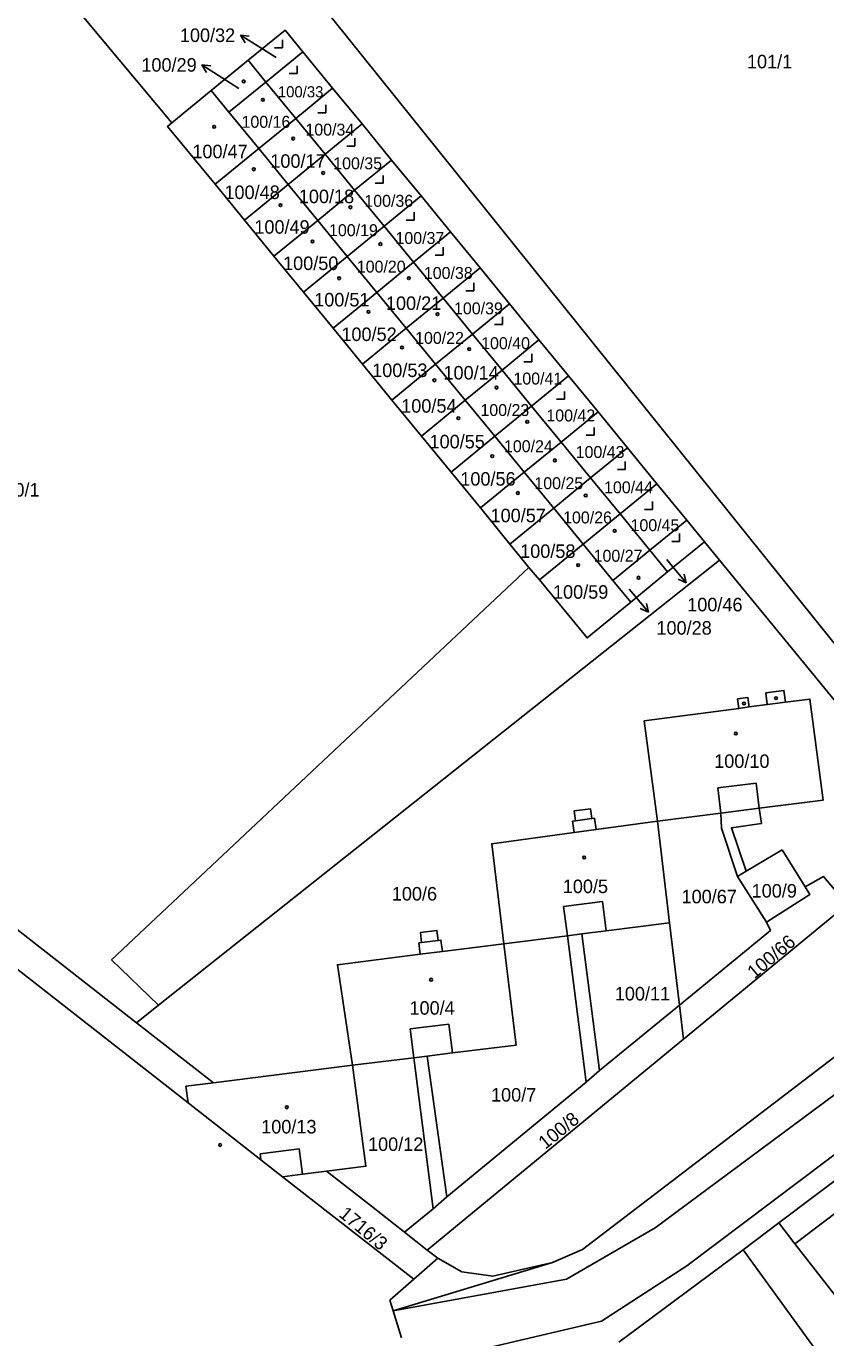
# Model space of a CAD drawing. Extents: x -724107 to -720612, y -1045267 to -1038441.
# Drawn here: x -723405.8 to -723305.3, y -1042643.6 to -1042478.7 of the extents above; entities that cross this region are included whole.
import ezdxf

# ---------------------------------------------------------------- set-up
doc = ezdxf.new("R2010")
doc.units = 0
for name, color, linetype in [('Hranice kat_území', 7, 'Continuous'), ('Hranice parcel', 7, 'Continuous'), ('Parcelní čísla', 7, 'Continuous'), ('Pop  PČ popisy', 7, 'Continuous'), ('Vnitřní kresba', 7, 'Continuous'), ('Značky budov', 7, 'Continuous'), ('Značky kultur', 7, 'Continuous')]:
    doc.layers.add(name, color=color, linetype=linetype)

msp = doc.modelspace()

# ---------------------------------------------------------------- linework, layer by layer
at = {"layer": 'Hranice kat_území'}
for p, q in [((-723432.73, -1042577.07), (-723385.46, -1042614.08)), ((-723373.58, -1042623.38), (-723357.09, -1042636.28)), ((-723357.09, -1042636.28), (-723360.11, -1042638.92))]:
    msp.add_line(p, q, dxfattribs=at)
for points in [[(-723373.58, -1042623.38), (-723376.31, -1042621.25), (-723385.46, -1042614.08)], [(-723360.11, -1042638.92), (-723359.7, -1042640.27), (-723358.63, -1042643.66)]]:
    msp.add_lwpolyline(points, dxfattribs=at)
at = {"layer": 'Hranice parcel'}
for p, q in [((-723387.48, -1042490.81), (-723402.99, -1042472.24)), ((-723375.68, -1042485.69), (-723371.04, -1042481.88)), ((-723371.04, -1042481.88), (-723367.29, -1042486.45)), ((-723377.91, -1042482.96), (-723382.55, -1042486.77)), ((-723375.68, -1042485.69), (-723377.91, -1042482.96)), ((-723375.68, -1042485.69), (-723380.32, -1042489.49)), ((-723371.93, -1042490.26), (-723375.68, -1042485.69)), ((-723387.48, -1042490.81), (-723382.55, -1042486.77)), ((-723382.55, -1042486.77), (-723380.32, -1042489.49)), ((-723371.93, -1042490.26), (-723367.29, -1042486.45)), ((-723367.29, -1042486.45), (-723363.59, -1042490.97)), ((-723380.32, -1042489.49), (-723376.57, -1042494.06)), ((-723376.57, -1042494.06), (-723371.93, -1042490.26)), ((-723368.23, -1042494.77), (-723371.93, -1042490.26)), ((-723368.23, -1042494.77), (-723363.59, -1042490.97)), ((-723363.59, -1042490.97), (-723359.88, -1042495.5)), ((-723382.07, -1042498.56), (-723376.57, -1042494.06)), ((-723376.57, -1042494.06), (-723372.87, -1042498.58)), ((-723372.87, -1042498.58), (-723368.23, -1042494.77)), ((-723364.53, -1042499.3), (-723368.23, -1042494.77)), ((-723364.53, -1042499.3), (-723359.88, -1042495.5)), ((-723359.88, -1042495.5), (-723356.18, -1042500.02)), ((-723378.36, -1042503.08), (-723382.07, -1042498.56)), ((-723378.36, -1042503.08), (-723372.87, -1042498.58)), ((-723372.87, -1042498.58), (-723369.17, -1042503.1)), ((-723369.17, -1042503.1), (-723364.53, -1042499.3)), ((-723360.82, -1042503.82), (-723364.53, -1042499.3)), ((-723360.82, -1042503.82), (-723356.18, -1042500.02)), ((-723356.18, -1042500.02), (-723352.47, -1042504.54)), ((-723374.66, -1042507.6), (-723378.36, -1042503.08)), ((-723374.66, -1042507.6), (-723369.17, -1042503.1)), ((-723369.17, -1042503.1), (-723365.46, -1042507.62)), ((-723365.46, -1042507.62), (-723360.82, -1042503.82)), ((-723357.11, -1042508.35), (-723360.82, -1042503.82)), ((-723357.11, -1042508.35), (-723352.47, -1042504.54)), ((-723352.47, -1042504.54), (-723348.76, -1042509.07)), ((-723370.95, -1042512.12), (-723374.66, -1042507.6)), ((-723370.95, -1042512.12), (-723365.46, -1042507.62)), ((-723365.46, -1042507.62), (-723361.75, -1042512.15)), ((-723361.75, -1042512.15), (-723357.11, -1042508.35)), ((-723353.4, -1042512.87), (-723357.11, -1042508.35)), ((-723353.4, -1042512.87), (-723348.76, -1042509.07)), ((-723348.76, -1042509.07), (-723345.05, -1042513.59)), ((-723367.24, -1042516.65), (-723370.95, -1042512.12)), ((-723367.24, -1042516.65), (-723361.75, -1042512.15)), ((-723361.75, -1042512.15), (-723358.04, -1042516.67)), ((-723358.04, -1042516.67), (-723353.4, -1042512.87)), ((-723349.7, -1042517.4), (-723353.4, -1042512.87)), ((-723349.7, -1042517.4), (-723345.05, -1042513.59)), ((-723345.05, -1042513.59), (-723341.35, -1042518.12)), ((-723363.53, -1042521.17), (-723367.24, -1042516.65)), ((-723363.53, -1042521.17), (-723358.04, -1042516.67)), ((-723358.04, -1042516.67), (-723354.34, -1042521.2)), ((-723349.7, -1042517.4), (-723354.34, -1042521.2)), ((-723345.99, -1042521.92), (-723349.7, -1042517.4)), ((-723345.99, -1042521.92), (-723341.35, -1042518.12)), ((-723341.35, -1042518.12), (-723337.64, -1042522.64)), ((-723359.83, -1042525.7), (-723363.53, -1042521.17)), ((-723359.83, -1042525.7), (-723354.34, -1042521.2)), ((-723354.34, -1042521.2), (-723350.63, -1042525.72)), ((-723350.63, -1042525.72), (-723345.99, -1042521.92)), ((-723342.28, -1042526.45), (-723345.99, -1042521.92)), ((-723342.28, -1042526.45), (-723337.64, -1042522.64)), ((-723337.64, -1042522.64), (-723333.93, -1042527.17)), ((-723356.12, -1042530.22), (-723359.83, -1042525.7)), ((-723356.12, -1042530.22), (-723350.63, -1042525.72)), ((-723350.63, -1042525.72), (-723346.92, -1042530.25)), ((-723346.92, -1042530.25), (-723342.28, -1042526.45)), ((-723338.57, -1042530.97), (-723342.28, -1042526.45)), ((-723338.57, -1042530.97), (-723333.93, -1042527.17)), ((-723333.93, -1042527.17), (-723330.22, -1042531.69)), ((-723352.41, -1042534.75), (-723356.12, -1042530.22)), ((-723352.41, -1042534.75), (-723346.92, -1042530.25)), ((-723346.92, -1042530.25), (-723343.21, -1042534.77)), ((-723343.21, -1042534.77), (-723338.57, -1042530.97)), ((-723334.86, -1042535.49), (-723338.57, -1042530.97)), ((-723334.86, -1042535.49), (-723330.22, -1042531.69)), ((-723330.22, -1042531.69), (-723326.52, -1042536.22)), ((-723348.7, -1042539.27), (-723352.41, -1042534.75)), ((-723348.7, -1042539.27), (-723343.21, -1042534.77)), ((-723343.21, -1042534.77), (-723339.49, -1042539.31)), ((-723339.49, -1042539.31), (-723334.86, -1042535.49)), ((-723331.16, -1042540.02), (-723334.86, -1042535.49)), ((-723331.16, -1042540.02), (-723326.52, -1042536.22)), ((-723326.52, -1042536.22), (-723322.77, -1042540.79)), ((-723345, -1042543.8), (-723348.7, -1042539.27)), ((-723345, -1042543.8), (-723339.49, -1042539.31)), ((-723339.49, -1042539.31), (-723335.8, -1042543.82)), ((-723335.8, -1042543.82), (-723331.16, -1042540.02)), ((-723327.41, -1042544.59), (-723331.16, -1042540.02)), ((-723327.41, -1042544.59), (-723322.77, -1042540.79)), ((-723322.77, -1042540.79), (-723320.54, -1042543.51)), ((-723325.18, -1042547.31), (-723320.54, -1042543.51)), ((-723342.61, -1042546.74), (-723345, -1042543.8)), ((-723341.29, -1042548.32), (-723335.8, -1042543.82)), ((-723335.8, -1042543.82), (-723332.05, -1042548.39)), ((-723332.05, -1042548.39), (-723327.41, -1042544.59)), ((-723325.18, -1042547.31), (-723327.41, -1042544.59)), ((-723342.61, -1042546.74), (-723341.29, -1042548.32)), ((-723332.05, -1042548.39), (-723329.82, -1042551.12)), ((-723329.82, -1042551.12), (-723325.18, -1042547.31)), ((-723318.48, -1042577.65), (-723326.47, -1042578.68)), ((-723318.48, -1042577.65), (-723313.67, -1042577.03)), ((-723326.47, -1042578.68), (-723324.94, -1042591.45)), ((-723310.8, -1042582.25), (-723307.88, -1042586.93)), ((-723316.38, -1042585.61), (-723312.74, -1042591.36)), ((-723324.94, -1042591.45), (-723323.7, -1042601.79)), ((-723345.76, -1042594.07), (-723337.78, -1042593.07)), ((-723337.78, -1042593.07), (-723335.95, -1042592.84)), ((-723323.19, -1042606.08), (-723323.7, -1042601.79)), ((-723382.28, -1042611.57), (-723391.94, -1042604.01)), ((-723323.19, -1042606.08), (-723355.39, -1042632.61)), ((-723364.8, -1042609.37), (-723382.28, -1042611.57)), ((-723364.8, -1042609.37), (-723357.1, -1042608.42)), ((-723357.1, -1042608.42), (-723355.4, -1042608.21)), ((-723300.57, -1042621.17), (-723311.19, -1042629.17)), ((-723311.19, -1042629.17), (-723315.69, -1042632.56)), ((-723358.24, -1042630.37), (-723355.39, -1042632.61)), ((-723354.07, -1042633.64), (-723355.39, -1042632.61)), ((-723315.69, -1042632.56), (-723331.32, -1042644.18)), ((-723315.69, -1042632.56), (-723280.06, -1042681.61)), ((-723354.07, -1042633.64), (-723357.09, -1042636.28))]:
    msp.add_line(p, q, dxfattribs=at)
for points in [[(-723278.64, -1042588.16), (-723334.54, -1042518.55), (-723369.16, -1042475.43), (-723362.99, -1042470.47), (-723371.61, -1042456.04)], [(-723377.91, -1042482.96), (-723373.27, -1042479.16), (-723371.04, -1042481.88)], [(-723382.07, -1042498.56), (-723388.04, -1042491.27), (-723387.48, -1042490.81)], [(-723320.54, -1042543.51), (-723318.65, -1042545.82), (-723281.64, -1042590.99)], [(-723391.94, -1042604.01), (-723389.18, -1042601.82), (-723395.07, -1042596.1), (-723342.61, -1042546.74)], [(-723341.29, -1042548.32), (-723335.31, -1042555.62), (-723329.82, -1042551.12)], [(-723474.38, -1042557.93), (-723460.4, -1042561.1), (-723444.26, -1042566.75), (-723430.26, -1042574.04), (-723391.94, -1042604.01)], [(-723313.67, -1042577.03), (-723305.63, -1042576), (-723307.3, -1042563.3), (-723310.37, -1042563.7), (-723310.57, -1042562.22), (-723312.85, -1042562.52), (-723312.65, -1042564), (-723314.93, -1042564.3), (-723315.09, -1042563.11), (-723316.38, -1042563.28), (-723316.22, -1042564.47), (-723328.13, -1042566.04), (-723326.47, -1042578.68)], [(-723326.47, -1042578.68), (-723334.17, -1042579.72), (-723334.37, -1042578.29), (-723334.71, -1042578.34), (-723334.88, -1042577.1), (-723336.94, -1042577.38), (-723336.78, -1042578.62), (-723337.12, -1042578.66), (-723336.93, -1042580.09), (-723347.29, -1042581.49), (-723345.76, -1042594.07)], [(-723318.48, -1042577.65), (-723318.41, -1042579.54), (-723316.38, -1042585.61)], [(-723313.67, -1042577.03), (-723313.4, -1042578.95), (-723317.16, -1042579.48), (-723315.29, -1042584.95), (-723310.8, -1042582.25)], [(-723307.88, -1042586.93), (-723305.58, -1042585.62), (-723302.61, -1042589.13), (-723323.19, -1042606.08)], [(-723312.74, -1042591.36), (-723307.29, -1042587.88), (-723307.88, -1042586.93)], [(-723335.95, -1042592.84), (-723332.89, -1042592.45), (-723324.94, -1042591.45)], [(-723323.7, -1042601.79), (-723312.27, -1042592.41), (-723312.74, -1042591.36)], [(-723345.76, -1042594.07), (-723353.5, -1042595.05), (-723353.68, -1042593.62), (-723354.03, -1042593.66), (-723354.19, -1042592.41), (-723356.26, -1042592.68), (-723356.1, -1042593.92), (-723356.45, -1042593.97), (-723356.27, -1042595.4), (-723366.68, -1042596.72), (-723364.8, -1042609.37)], [(-723355.4, -1042608.21), (-723352.93, -1042625.91), (-723335.41, -1042611.47), (-723337.78, -1042593.07)], [(-723323.7, -1042601.79), (-723333.75, -1042610.04), (-723335.95, -1042592.84)], [(-723355.4, -1042608.21), (-723352.22, -1042607.81), (-723344.24, -1042606.82), (-723345.76, -1042594.07)], [(-723294.52, -1042600.92), (-723335.88, -1042632.52), (-723339.65, -1042634.17), (-723347.17, -1042635.89), (-723351.03, -1042635.33), (-723354.07, -1042633.64)], [(-723364.8, -1042609.37), (-723363.1, -1042622.06), (-723368.08, -1042622.68)], [(-723357.1, -1042608.42), (-723354.65, -1042627.43), (-723358.24, -1042630.37)], [(-723382.28, -1042611.57), (-723385.74, -1042612.01), (-723385.46, -1042614.08)], [(-723373.58, -1042623.38), (-723371.09, -1042623.06), (-723368.08, -1042622.68)], [(-723368.08, -1042622.68), (-723362.42, -1042627.1), (-723358.24, -1042630.37)], [(-723287.28, -1042639.43), (-723289.61, -1042641.12), (-723289.94, -1042640.64), (-723294.84, -1042644.9), (-723297.04, -1042644.34), (-723301.77, -1042638.11), (-723303.31, -1042639.32), (-723309.2, -1042631.82), (-723311.19, -1042629.17)]]:
    msp.add_lwpolyline(points, dxfattribs=at)
at = {"layer": 'Pop  PČ popisy'}
for p, q in [((-723376.33, -1042481.4), (-723378.88, -1042479.81)), ((-723378.88, -1042479.81), (-723377.76, -1042479.92)), ((-723378.88, -1042479.81), (-723378.29, -1042480.77)), ((-723374.4, -1042482.6), (-723376.33, -1042481.4)), ((-723381.19, -1042485.16), (-723383.71, -1042483.53)), ((-723383.71, -1042483.53), (-723382.59, -1042483.65)), ((-723383.71, -1042483.53), (-723383.14, -1042484.49)), ((-723379.09, -1042486.51), (-723381.19, -1042485.16)), ((-723325.28, -1042545.76), (-723324.77, -1042546.38)), ((-723324.77, -1042546.38), (-723322.84, -1042548.68)), ((-723322.84, -1042548.68), (-723323.87, -1042548.23)), ((-723322.84, -1042548.68), (-723323.1, -1042547.59)), ((-723330.01, -1042549.5), (-723329.52, -1042550.08)), ((-723329.52, -1042550.08), (-723327.59, -1042552.38)), ((-723327.59, -1042552.38), (-723327.85, -1042551.29)), ((-723327.59, -1042552.38), (-723328.62, -1042551.93))]:
    msp.add_line(p, q, dxfattribs=at)
at = {"layer": 'Vnitřní kresba'}
for p, q in [((-723389.18, -1042601.82), (-723318.65, -1042545.82)), ((-723326.74, -1042629.82), (-723233.53, -1042560.48)), ((-723316.22, -1042564.47), (-723314.93, -1042564.3)), ((-723312.65, -1042564), (-723310.37, -1042563.7)), ((-723322.77, -1042634.57), (-723231.75, -1042565.97)), ((-723318.89, -1042574.47), (-723314.07, -1042573.86)), ((-723318.48, -1042577.65), (-723318.89, -1042574.47)), ((-723314.07, -1042573.86), (-723313.67, -1042577.03)), ((-723336.93, -1042580.09), (-723334.17, -1042579.72)), ((-723336.78, -1042578.62), (-723334.71, -1042578.34)), ((-723316.38, -1042585.61), (-723315.29, -1042584.95)), ((-723338.25, -1042589.38), (-723333.36, -1042588.76)), ((-723337.78, -1042593.07), (-723338.25, -1042589.38)), ((-723333.36, -1042588.76), (-723332.89, -1042592.45)), ((-723356.1, -1042593.92), (-723354.03, -1042593.66)), ((-723356.27, -1042595.4), (-723353.5, -1042595.05)), ((-723352.67, -1042604.19), (-723357.55, -1042604.8)), ((-723352.22, -1042607.81), (-723352.67, -1042604.19)), ((-723357.55, -1042604.8), (-723357.1, -1042608.42)), ((-723335.41, -1042611.47), (-723333.75, -1042610.04)), ((-723371.49, -1042619.89), (-723376.4, -1042620.51)), ((-723376.4, -1042620.51), (-723376.31, -1042621.25)), ((-723371.09, -1042623.06), (-723371.49, -1042619.89)), ((-723354.65, -1042627.43), (-723352.93, -1042625.91)), ((-723309.2, -1042631.82), (-723301.51, -1042625.97)), ((-723337.88, -1042636.28), (-723326.74, -1042629.82)), ((-723359.7, -1042640.27), (-723339.65, -1042634.17)), ((-723322.77, -1042634.57), (-723333.49, -1042641.53)), ((-723337.88, -1042636.28), (-723359.7, -1042640.27)), ((-723333.49, -1042641.53), (-723357.59, -1042647.22))]:
    msp.add_line(p, q, dxfattribs=at)
at = {"layer": 'Značky budov'}
for centre in [(-723378.47, -1042485.61), (-723376.06, -1042487.93), (-723382.19, -1042491.33), (-723372.25, -1042492.81), (-723377.2, -1042496.67), (-723368.47, -1042497.13), (-723373.84, -1042501.19), (-723365.06, -1042501.45), (-723369.83, -1042505.76), (-723361.29, -1042506.07), (-723366.47, -1042510.38), (-723357.71, -1042510.37), (-723362.79, -1042514.61), (-723354.1, -1042514.9), (-723358.57, -1042519.08), (-723350.12, -1042519.28), (-723354.5, -1042523.21), (-723346.68, -1042524.13), (-723351.49, -1042527.97), (-723342.82, -1042528.42), (-723347.22, -1042532.75), (-723339.35, -1042533.28), (-723344, -1042537.39), (-723335.48, -1042537.71), (-723331.84, -1042542.13), (-723336.43, -1042546.45), (-723328.83, -1042548.04), (-723311.56, -1042563.19), (-723315.58, -1042563.85), (-723316.61, -1042567.64), (-723335.66, -1042583.22), (-723354.92, -1042598.6), (-723373.05, -1042614.65), (-723381.43, -1042619.39)]:
    msp.add_circle(centre, 0.175, dxfattribs=at)
at = {"layer": 'Značky kultur'}
for p, q in [((-723373.6, -1042481.4), (-723373.6, -1042480.4)), ((-723374.6, -1042481.4), (-723373.6, -1042481.4)), ((-723371.74, -1042484.64), (-723371.74, -1042483.64)), ((-723372.74, -1042484.64), (-723371.74, -1042484.64)), ((-723368.13, -1042489.57), (-723368.13, -1042488.57)), ((-723369.13, -1042489.57), (-723368.13, -1042489.57)), ((-723365.51, -1042493.74), (-723364.51, -1042493.74)), ((-723364.51, -1042493.74), (-723364.51, -1042492.74)), ((-723360.93, -1042498.43), (-723360.93, -1042497.43)), ((-723361.93, -1042498.43), (-723360.93, -1042498.43)), ((-723357.04, -1042503.05), (-723357.04, -1042502.05)), ((-723358.04, -1042503.05), (-723357.04, -1042503.05)), ((-723353.38, -1042507.47), (-723353.38, -1042506.47)), ((-723354.38, -1042507.47), (-723353.38, -1042507.47)), ((-723350.56, -1042511.96), (-723349.56, -1042511.96)), ((-723349.56, -1042511.96), (-723349.56, -1042510.96)), ((-723345.95, -1042516.21), (-723345.95, -1042515.21)), ((-723346.95, -1042516.21), (-723345.95, -1042516.21)), ((-723342.25, -1042520.87), (-723342.25, -1042519.87)), ((-723343.25, -1042520.87), (-723342.25, -1042520.87)), ((-723338.13, -1042525.6), (-723338.13, -1042524.6)), ((-723339.13, -1042525.6), (-723338.13, -1042525.6)), ((-723335.4, -1042530.13), (-723334.4, -1042530.13)), ((-723334.4, -1042530.13), (-723334.4, -1042529.13)), ((-723330.5, -1042534.43), (-723330.5, -1042533.43)), ((-723331.5, -1042534.43), (-723330.5, -1042534.43)), ((-723327.08, -1042539.44), (-723327.08, -1042538.44)), ((-723328.08, -1042539.44), (-723327.08, -1042539.44)), ((-723324.67, -1042543.49), (-723323.67, -1042543.49)), ((-723323.67, -1042543.49), (-723323.67, -1042542.49))]:
    msp.add_line(p, q, dxfattribs=at)

# ---------------------------------------------------------------- texts
at = {"layer": 'Parcelní čísla'}
for s, height, p in [('100/32', 1.7, (-723386.49, -1042480.66)), ('100/29', 1.7, (-723391.33, -1042484.39)), ('101/1', 1.7, (-723315.21, -1042483.97)), ('100/33', 1.4, (-723374.17, -1042487.62)), ('100/16', 1.5, (-723378.74, -1042491.45)), ('100/34', 1.5, (-723370.71, -1042492.43)), ('100/47', 1.7, (-723384.92, -1042495.28)), ('100/17', 1.7, (-723375.12, -1042496.48)), ('100/35', 1.5, (-723367.21, -1042496.67)), ('100/48', 1.7, (-723380.89, -1042500.41)), ('100/18', 1.7, (-723371.54, -1042500.93)), ('100/36', 1.5, (-723363.3, -1042501.39)), ('100/49', 1.7, (-723377.13, -1042504.77)), ('100/19', 1.5, (-723367.74, -1042505.08)), ('100/37', 1.5, (-723359.39, -1042506.06)), ('100/50', 1.7, (-723373.52, -1042509.34)), ('100/20', 1.5, (-723364.25, -1042509.66)), ('100/38', 1.5, (-723355.82, -1042510.46)), ('100/51', 1.7, (-723369.61, -1042513.92)), ('100/21', 1.7, (-723360.59, -1042514.36)), ('100/39', 1.5, (-723352.03, -1042514.91)), ('100/52', 1.7, (-723366.19, -1042518.27)), ('100/22', 1.5, (-723356.92, -1042518.63)), ('100/40', 1.5, (-723348.62, -1042519.29)), ('100/53', 1.7, (-723362.32, -1042522.8)), ('100/14', 1.7, (-723353.36, -1042523.11)), ('100/41', 1.5, (-723344.56, -1042523.74)), ('100/54', 1.7, (-723358.67, -1042527.28)), ('100/23', 1.5, (-723348.71, -1042527.7)), ('100/42', 1.5, (-723340.42, -1042528.38)), ('100/55', 1.7, (-723355.11, -1042531.77)), ('100/24', 1.5, (-723345.75, -1042532.25)), ('100/43', 1.5, (-723336.74, -1042532.98)), ('100/56', 1.7, (-723351.24, -1042536.46)), ('100/25', 1.5, (-723341.93, -1042536.9)), ('100/1', 1.7, (-723409.82, -1042537.84)), ('100/44', 1.5, (-723333.17, -1042537.42)), ('100/57', 1.7, (-723347.44, -1042541.06)), ('100/26', 1.5, (-723338.32, -1042541.21)), ('100/45', 1.5, (-723329.84, -1042542.18)), ('100/58', 1.7, (-723343.72, -1042545.55)), ('100/27', 1.5, (-723334.48, -1042546.03)), ('100/59', 1.7, (-723339.59, -1042550.68)), ('100/46', 1.7, (-723322.72, -1042552.27)), ('100/28', 1.7, (-723326.59, -1042555.2)), ('100/10', 1.7, (-723319.33, -1042571.96)), ('100/5', 1.7, (-723338.36, -1042587.71)), ('100/9', 1.7, (-723314.62, -1042588.27)), ('100/6', 1.7, (-723359.85, -1042588.64)), ('100/67', 1.7, (-723323.43, -1042588.99)), ('100/11', 1.7, (-723331.82, -1042601.21)), ('100/4', 1.7, (-723357.63, -1042603)), ('100/7', 1.7, (-723347.38, -1042613.93)), ('100/13', 1.7, (-723376.27, -1042617.94)), ('100/12', 1.7, (-723362.84, -1042620.14))]:
    msp.add_text(s, height=height, dxfattribs=at).set_placement(p)
for s, rotation, p in [('100/66', 40, (-723314.28, -1042598.58)), ('100/8', 39, (-723340.56, -1042620.01)), ('1716/3', 320, (-723366.62, -1042628.28))]:
    msp.add_text(s, height=1.7, rotation=rotation, dxfattribs=at).set_placement(p)

doc.saveas('drawing.dxf')
